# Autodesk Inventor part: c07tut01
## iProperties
Shininess: 77.0
Length Units: 11269
Angle Units: 11279
Time Units: 11290
Mass Units: 11283
Length Display Precision: 3
Angle Display Precision: 2
Created: 2002-01
Part Number: c07tut01
Document SubType Name: Modeling
Designer: ***
Density: 1 g/cm^3
Density: 0.0
Volumn: 0.0
Area: 0.0
PropertySet Name: Model Information
Control State: 0
Master: False
Checked Out: False
Author: ***
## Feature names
1. Sweep1
2. Shell1
3. Extrusion1
4. Extrusion2
5. Hole1
6. Fillet1
7. Extrusion3
8. Extrusion4
9. Hole2
10. Hole3
11. Circular Pattern1
12. Circular Pattern2
13. Hole4
